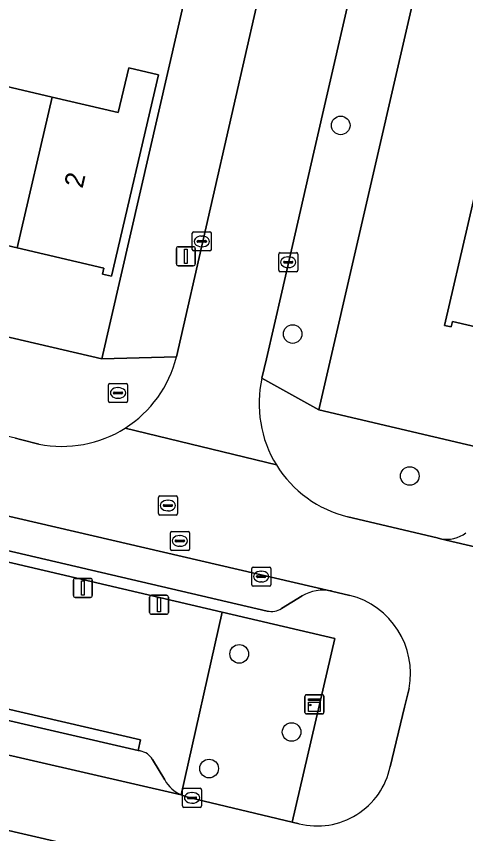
# Model space of a CAD drawing. Extents: x 163683 to 164494, y 382709 to 383872.
# Drawn here: x 163890.12 to 163913.7, y 383325.1 to 383367.98 of the extents above; entities that cross this region are included whole.
import ezdxf

# ---------------------------------------------------------------- set-up
doc = ezdxf.new("R2010")
doc.units = 0
for name, color, linetype in [('IMGEO_Boom', 7, 'Continuous'), ('IMGEO_Brandkraan', 7, 'Continuous'), ('IMGEO_Erf', 7, 'Continuous'), ('IMGEO_Groenvoorziening', 7, 'Continuous'), ('IMGEO_Kast', 7, 'Continuous'), ('IMGEO_Kolk', 7, 'Continuous'), ('IMGEO_Lichtmast', 7, 'Continuous'), ('IMGEO_Pand', 7, 'Continuous'), ('IMGEO_Pand_nummerreeks', 7, 'Continuous'), ('IMGEO_Parkeervlak_open', 7, 'Continuous'), ('IMGEO_Rijbaan_lokaal_open', 7, 'Continuous'), ('IMGEO_Rioolput', 7, 'Continuous'), ('IMGEO_Verkeersbordpaal', 7, 'Continuous'), ('IMGEO_Voetpad_open', 7, 'Continuous')]:
    doc.layers.add(name, color=color, linetype=linetype)

msp = doc.modelspace()

# ---------------------------------------------------------------- linework, layer by layer
at = {"layer": 'IMGEO_Boom'}
for centre in [(163907.144, 383362.255), (163904.622, 383351.31), (163910.77, 383343.861), (163901.817, 383334.529), (163904.566, 383330.431), (163900.236, 383328.514)]:
    msp.add_circle(centre, 0.489, dxfattribs=at)
at = {"layer": 'IMGEO_Brandkraan'}
for p, q in [((163894.955, 383347.792), (163894.955, 383348.644)), ((163895.03, 383348.718), (163895.882, 383348.718)), ((163895.443, 383348.498), (163895.468, 383348.498)), ((163895.956, 383348.644), (163895.956, 383347.792)), ((163895.214, 383348.212), (163895.214, 383348.224)), ((163895.652, 383348.175), (163895.254, 383348.175)), ((163895.257, 383348.261), (163895.655, 383348.261)), ((163895.698, 383348.224), (163895.698, 383348.212)), ((163895.882, 383347.718), (163895.03, 383347.718)), ((163895.466, 383347.938), (163895.441, 383347.938))]:
    msp.add_line(p, q, dxfattribs=at)
for points in [[(163894.955, 383347.792), (163894.955, 383348.644)], [(163895.03, 383348.718), (163895.882, 383348.718)], [(163895.956, 383348.644), (163895.956, 383347.792)], [(163895.882, 383347.718), (163895.03, 383347.718)]]:
    msp.add_lwpolyline(points, dxfattribs=at)
for centre, radius, start, end in [((163895.032, 383348.642), 0.0765, 91.552, 178.448), ((163895.032, 383348.642), 0.0765, 91.552, 178.448), ((163895.88, 383348.642), 0.0765, 1.552, 88.448), ((163895.88, 383348.642), 0.0765, 1.552, 88.448), ((163895.254, 383348.221), 0.0403, 85.8775, 175.7526), ((163895.251, 383348.211), 0.0366, 178.938, 274.7102), ((163895.655, 383348.218), 0.043, 264.8664, 352.4533), ((163895.659, 383348.223), 0.0386, 1.7309, 96.639), ((163895.032, 383347.794), 0.0765, 181.552, 268.448), ((163895.032, 383347.794), 0.0765, 181.552, 268.448), ((163895.88, 383347.794), 0.0765, 271.552, 358.448), ((163895.88, 383347.794), 0.0765, 271.552, 358.448)]:
    msp.add_arc(centre, radius, start, end, dxfattribs=at)
for centre, major_axis, ratio, start_param, end_param in [((163895.442, 383348.218), (-0.387, 0.002), 0.722429, 4.712389, 7.853982), ((163895.467, 383348.218), (-0.39, 0.002), 0.717154, 1.570796, 4.712389)]:
    msp.add_ellipse(centre, major_axis=major_axis, ratio=ratio, start_param=start_param, end_param=end_param, dxfattribs=at)
at = {"layer": 'IMGEO_Erf'}
for points in [[(163917.712, 383398.152), (163905.989, 383347.327), (163957.118, 383335.345)], [(163842.87, 383362.042), (163894.598, 383350.001), (163899.567, 383371.61)], [(163888.929, 383364.459), (163892.005, 383363.742), (163895.47, 383362.935), (163896.016, 383365.272), (163897.574, 383364.908), (163895.107, 383354.342), (163894.636, 383354.452), (163894.71, 383354.77), (163890.16, 383355.832), (163885.53, 383356.913)], [(163921.455, 383350.012), (163913.015, 383351.973), (163912.947, 383351.679), (163912.585, 383351.763), (163915.07, 383362.459)]]:
    msp.add_lwpolyline(points, dxfattribs=at)
at = {"layer": 'IMGEO_Groenvoorziening'}
for points in [[(163898.763, 383327.134), (163900.929, 383336.712), (163868.463, 383344.309), (163866.185, 383334.632), (163868.028, 383334.196), (163868.2, 383334.169)], [(163871.285, 383335.287), (163871.432, 383335.858), (163896.634, 383330.025), (163896.512, 383329.468), (163896.623, 383329.442)], [(163897.268, 383328.982), (163897.91, 383327.916)]]:
    msp.add_lwpolyline(points, dxfattribs=at)
msp.add_lwpolyline([(163906.833, 383335.33), (163900.929, 383336.712), (163898.763, 383327.134), (163899.046, 383327.03), (163899.172, 383326.999), (163904.594, 383325.708)], close=True, dxfattribs=at)
for centre, radius, start, end in [((163896.43, 383328.489), 0.972, 30.4652, 78.5436), ((163899.55, 383328.848), 1.886, 209.6209, 245.3521)]:
    msp.add_arc(centre, radius, start, end, dxfattribs=at)
at = {"layer": 'IMGEO_Kast'}
for p, q in [((163905.266, 383331.456), (163905.266, 383332.297)), ((163905.266, 383332.297), (163905.266, 383331.456)), ((163905.341, 383332.381), (163906.182, 383332.381)), ((163906.182, 383332.381), (163905.341, 383332.381)), ((163906.266, 383332.306), (163906.266, 383331.465)), ((163906.266, 383331.465), (163906.266, 383332.306)), ((163906.191, 383331.381), (163905.35, 383331.381)), ((163905.35, 383331.381), (163906.191, 383331.381))]:
    msp.add_line(p, q, dxfattribs=at)
for points in [[(163905.461, 383332.171), (163906.061, 383332.171), (163906.061, 383332.086), (163905.461, 383332.086), (163905.461, 383332.171)], [(163905.461, 383331.996), (163906.061, 383331.996), (163906.061, 383331.507), (163905.461, 383331.507), (163905.461, 383331.996)]]:
    msp.add_lwpolyline(points, dxfattribs=at)
msp.add_circle((163905.545, 383331.845), 0.0377, dxfattribs=at)
for centre, start, end in [((163905.344, 383332.303), 92.4484, 184.2845), ((163905.344, 383332.303), 92.4484, 184.2845), ((163906.188, 383332.303), 2.4484, 94.2845), ((163906.188, 383332.303), 2.4484, 94.2845), ((163905.344, 383331.459), 182.4484, 274.2845), ((163905.344, 383331.459), 182.4484, 274.2845), ((163906.188, 383331.459), 272.4484, 4.2845), ((163906.188, 383331.459), 272.4484, 4.2845)]:
    msp.add_arc(centre, 0.0779, start, end, dxfattribs=at)
at = {"layer": 'IMGEO_Kolk'}
for p, q in [((163899.352, 383355.744), (163899.352, 383356.596)), ((163899.427, 383356.67), (163900.279, 383356.67)), ((163900.353, 383356.596), (163900.353, 383355.744)), ((163899.611, 383356.164), (163899.611, 383356.176)), ((163899.654, 383356.213), (163900.052, 383356.213)), ((163899.84, 383356.45), (163899.865, 383356.45)), ((163900.095, 383356.176), (163900.095, 383356.164)), ((163900.049, 383356.127), (163899.651, 383356.127)), ((163899.863, 383355.89), (163899.838, 383355.89)), ((163900.279, 383355.67), (163899.427, 383355.67)), ((163903.889, 383354.652), (163903.889, 383355.504)), ((163903.964, 383355.578), (163904.816, 383355.578)), ((163904.377, 383355.358), (163904.402, 383355.358)), ((163904.89, 383355.504), (163904.89, 383354.652)), ((163904.148, 383355.072), (163904.148, 383355.084)), ((163904.586, 383355.035), (163904.188, 383355.035)), ((163904.191, 383355.121), (163904.589, 383355.121)), ((163904.632, 383355.084), (163904.632, 383355.072)), ((163904.816, 383354.578), (163903.964, 383354.578)), ((163904.4, 383354.798), (163904.375, 383354.798)), ((163902.472, 383338.16), (163902.472, 383339.012)), ((163902.547, 383339.086), (163903.399, 383339.086)), ((163903.473, 383339.012), (163903.473, 383338.16)), ((163902.731, 383338.58), (163902.731, 383338.592)), ((163902.774, 383338.629), (163903.172, 383338.629)), ((163902.96, 383338.866), (163902.985, 383338.866)), ((163903.215, 383338.592), (163903.215, 383338.58)), ((163903.169, 383338.543), (163902.771, 383338.543)), ((163902.983, 383338.306), (163902.958, 383338.306)), ((163903.399, 383338.086), (163902.547, 383338.086)), ((163898.915, 383327.476), (163899.767, 383327.476)), ((163898.84, 383326.55), (163898.84, 383327.402)), ((163899.142, 383327.019), (163899.54, 383327.019)), ((163899.328, 383327.256), (163899.353, 383327.256)), ((163899.841, 383327.402), (163899.841, 383326.55)), ((163899.099, 383326.97), (163899.099, 383326.982)), ((163899.537, 383326.933), (163899.139, 383326.933)), ((163899.351, 383326.696), (163899.326, 383326.696)), ((163899.583, 383326.982), (163899.583, 383326.97)), ((163899.767, 383326.476), (163898.915, 383326.476))]:
    msp.add_line(p, q, dxfattribs=at)
for points in [[(163899.352, 383355.744), (163899.352, 383356.596)], [(163899.427, 383356.67), (163900.279, 383356.67)], [(163900.353, 383356.596), (163900.353, 383355.744)], [(163900.279, 383355.67), (163899.427, 383355.67)], [(163903.889, 383354.652), (163903.889, 383355.504)], [(163903.964, 383355.578), (163904.816, 383355.578)], [(163904.89, 383355.504), (163904.89, 383354.652)], [(163904.816, 383354.578), (163903.964, 383354.578)], [(163902.472, 383338.16), (163902.472, 383339.012)], [(163902.547, 383339.086), (163903.399, 383339.086)], [(163903.473, 383339.012), (163903.473, 383338.16)], [(163903.399, 383338.086), (163902.547, 383338.086)], [(163898.915, 383327.476), (163899.767, 383327.476)], [(163898.84, 383326.55), (163898.84, 383327.402)], [(163899.841, 383327.402), (163899.841, 383326.55)], [(163899.767, 383326.476), (163898.915, 383326.476)]]:
    msp.add_lwpolyline(points, dxfattribs=at)
for centre, radius, start, end in [((163899.429, 383356.594), 0.0765, 91.552, 178.448), ((163899.429, 383356.594), 0.0765, 91.552, 178.448), ((163900.277, 383356.594), 0.0765, 1.552, 88.448), ((163900.277, 383356.594), 0.0765, 1.552, 88.448), ((163899.651, 383356.173), 0.0403, 85.8775, 175.7526), ((163899.648, 383356.163), 0.0366, 178.938, 274.7102), ((163900.052, 383356.17), 0.043, 264.8664, 352.4533), ((163900.056, 383356.175), 0.0386, 1.7309, 96.639), ((163899.429, 383355.746), 0.0765, 181.552, 268.448), ((163899.429, 383355.746), 0.0765, 181.552, 268.448), ((163900.277, 383355.746), 0.0765, 271.552, 358.448), ((163900.277, 383355.746), 0.0765, 271.552, 358.448), ((163903.966, 383355.502), 0.0765, 91.552, 178.448), ((163903.966, 383355.502), 0.0765, 91.552, 178.448), ((163904.814, 383355.502), 0.0765, 1.552, 88.448), ((163904.814, 383355.502), 0.0765, 1.552, 88.448), ((163904.188, 383355.081), 0.0403, 85.8775, 175.7526), ((163904.185, 383355.071), 0.0366, 178.938, 274.7102), ((163904.589, 383355.078), 0.043, 264.8664, 352.4533), ((163904.593, 383355.083), 0.0386, 1.7309, 96.639), ((163903.966, 383354.654), 0.0765, 181.552, 268.448), ((163903.966, 383354.654), 0.0765, 181.552, 268.448), ((163904.814, 383354.654), 0.0765, 271.552, 358.448), ((163904.814, 383354.654), 0.0765, 271.552, 358.448), ((163902.549, 383339.01), 0.0765, 91.552, 178.448), ((163902.549, 383339.01), 0.0765, 91.552, 178.448), ((163903.397, 383339.01), 0.0765, 1.552, 88.448), ((163903.397, 383339.01), 0.0765, 1.552, 88.448), ((163902.771, 383338.589), 0.0403, 85.8775, 175.7526), ((163902.768, 383338.579), 0.0366, 178.938, 274.7102), ((163903.172, 383338.586), 0.043, 264.8664, 352.4533), ((163903.176, 383338.591), 0.0386, 1.7309, 96.639), ((163902.549, 383338.162), 0.0765, 181.552, 268.448), ((163902.549, 383338.162), 0.0765, 181.552, 268.448), ((163903.397, 383338.162), 0.0765, 271.552, 358.448), ((163903.397, 383338.162), 0.0765, 271.552, 358.448), ((163898.917, 383327.4), 0.0765, 91.552, 178.448), ((163898.917, 383327.4), 0.0765, 91.552, 178.448), ((163899.765, 383327.4), 0.0765, 1.552, 88.448), ((163899.765, 383327.4), 0.0765, 1.552, 88.448), ((163899.139, 383326.979), 0.0403, 85.8775, 175.7526), ((163899.544, 383326.981), 0.0386, 1.7309, 96.639), ((163899.136, 383326.969), 0.0366, 178.938, 274.7102), ((163899.54, 383326.976), 0.043, 264.8664, 352.4533), ((163898.917, 383326.552), 0.0765, 181.552, 268.448), ((163898.917, 383326.552), 0.0765, 181.552, 268.448), ((163899.765, 383326.552), 0.0765, 271.552, 358.448), ((163899.765, 383326.552), 0.0765, 271.552, 358.448)]:
    msp.add_arc(centre, radius, start, end, dxfattribs=at)
for centre, major_axis, ratio, start_param, end_param in [((163899.839, 383356.17), (-0.387, 0.002), 0.722429, 4.712389, 7.853982), ((163899.864, 383356.17), (-0.39, 0.002), 0.717154, 1.570796, 4.712389), ((163904.376, 383355.078), (-0.387, 0.002), 0.722429, 4.712389, 7.853982), ((163904.401, 383355.078), (-0.39, 0.002), 0.717154, 1.570796, 4.712389), ((163902.959, 383338.586), (-0.387, 0.002), 0.722429, 4.712389, 7.853982), ((163902.984, 383338.586), (-0.39, 0.002), 0.717154, 1.570796, 4.712389), ((163899.327, 383326.976), (-0.387, 0.002), 0.722429, 4.712389, 7.853982), ((163899.352, 383326.976), (-0.39, 0.002), 0.717154, 1.570796, 4.712389)]:
    msp.add_ellipse(centre, major_axis=major_axis, ratio=ratio, start_param=start_param, end_param=end_param, dxfattribs=at)
at = {"layer": 'IMGEO_Lichtmast'}
for p, q in [((163898.518, 383354.989), (163898.518, 383355.789)), ((163898.518, 383355.789), (163898.518, 383354.989)), ((163898.618, 383355.889), (163899.408, 383355.889)), ((163899.408, 383355.889), (163898.618, 383355.889)), ((163899.508, 383355.789), (163899.508, 383354.989)), ((163899.508, 383354.989), (163899.508, 383355.789)), ((163899.408, 383354.889), (163898.618, 383354.889)), ((163898.618, 383354.889), (163899.408, 383354.889)), ((163893.113, 383337.59), (163893.113, 383338.39)), ((163893.113, 383338.39), (163893.113, 383337.59)), ((163893.213, 383338.49), (163894.003, 383338.49)), ((163894.003, 383338.49), (163893.213, 383338.49)), ((163894.103, 383338.39), (163894.103, 383337.59)), ((163894.103, 383337.59), (163894.103, 383338.39)), ((163894.003, 383337.49), (163893.213, 383337.49)), ((163893.213, 383337.49), (163894.003, 383337.49))]:
    msp.add_line(p, q, dxfattribs=at)
for points in [[(163898.938, 383355.764), (163899.088, 383355.764), (163899.088, 383355.014), (163898.938, 383355.014), (163898.938, 383355.764)], [(163893.533, 383338.365), (163893.683, 383338.365), (163893.683, 383337.615), (163893.533, 383337.615), (163893.533, 383338.365)]]:
    msp.add_lwpolyline(points, dxfattribs=at)
for centre, start, end in [((163898.618, 383355.789), 90, 180), ((163898.618, 383355.789), 90, 180), ((163899.408, 383355.789), 0, 90), ((163899.408, 383355.789), 360, 90), ((163898.618, 383354.989), 180, 270), ((163898.618, 383354.989), 180, 270), ((163899.408, 383354.989), 270, 0), ((163899.408, 383354.989), 270, 0), ((163893.213, 383338.39), 90, 180), ((163893.213, 383338.39), 90, 180), ((163894.003, 383338.39), 0, 90), ((163894.003, 383338.39), 360, 90), ((163893.213, 383337.59), 180, 270), ((163893.213, 383337.59), 180, 270), ((163894.003, 383337.59), 270, 0), ((163894.003, 383337.59), 270, 0)]:
    msp.add_arc(centre, 0.1, start, end, dxfattribs=at)
at = {"layer": 'IMGEO_Pand'}
for points in [[(163892.005, 383363.742), (163888.929, 383364.459), (163889.4, 383366.48), (163889.444, 383366.669), (163887.869, 383367.036), (163885.53, 383356.913), (163890.16, 383355.832)], [(163890.16, 383355.832), (163894.71, 383354.77), (163894.636, 383354.452), (163895.107, 383354.342), (163897.574, 383364.908), (163896.016, 383365.272), (163895.47, 383362.935), (163892.005, 383363.742)]]:
    msp.add_lwpolyline(points, close=True, dxfattribs=at)
msp.add_lwpolyline([(163915.07, 383362.459), (163912.585, 383351.763), (163912.947, 383351.679), (163913.015, 383351.973), (163921.455, 383350.012)], dxfattribs=at)
at = {"layer": 'IMGEO_Parkeervlak_open'}
for points in [[(163906.662, 383337.828), (163862.998, 383347.946)], [(163865.26, 383345.632), (163903.288, 383336.778)], [(163912.387, 383340.568), (163969.564, 383327.202)], [(163904.041, 383336.912), (163905.116, 383337.567)], [(163896.623, 383329.442), (163896.512, 383329.468), (163871.285, 383335.287)], [(163868.2, 383334.169), (163898.763, 383327.134)], [(163902.326, 383322.351), (163859.76, 383332.184)], [(163897.91, 383327.916), (163897.268, 383328.982)]]:
    msp.add_lwpolyline(points, dxfattribs=at)
for centre, radius, start, end in [((163912.698, 383342.215), 1.676, 259.3128, 307.3126), ((163906.228, 383335.687), 2.185, 78.5544, 120.6105), ((163903.501, 383337.765), 1.01, 257.8345, 302.3464), ((163896.43, 383328.489), 0.972, 30.4652, 78.5436), ((163899.55, 383328.848), 1.886, 209.6209, 245.3521)]:
    msp.add_arc(centre, radius, start, end, dxfattribs=at)
at = {"layer": 'IMGEO_Rijbaan_lokaal_open'}
for points in [[(163910.714, 383382.502), (163911.484, 383385.85), (163913.281, 383393.665), (163913.354, 383393.969), (163908.819, 383395.067), (163904.084, 383374.498), (163903.189, 383370.591), (163898.523, 383350.105)], [(163903.008, 383348.996), (163903.248, 383350.007), (163904.046, 383353.505), (163905.734, 383360.846), (163906.504, 383364.194), (163910.714, 383382.502)], [(163891.307, 383345.538), (163890.343, 383345.775), (163890.075, 383345.852), (163813.016, 383363.779), (163811.969, 383364.028)], [(163862.374, 383348.112), (163862.998, 383347.946), (163906.662, 383337.828), (163907.619, 383337.6)], [(163895.831, 383346.374), (163903.774, 383344.439)], [(163903.774, 383344.439), (163895.831, 383346.374)], [(163973.151, 383326.354), (163969.754, 383327.157), (163969.564, 383327.202), (163912.387, 383340.568), (163912.213, 383340.611), (163907.514, 383341.726)], [(163904.957, 383325.621), (163904.594, 383325.708), (163899.172, 383326.999), (163899.046, 383327.03), (163898.763, 383327.134), (163868.2, 383334.169), (163868.028, 383334.196), (163866.185, 383334.632), (163859.195, 383336.276)], [(163910.733, 383332.715), (163910.487, 383331.736), (163909.74, 383328.609)], [(163858.996, 383332.399), (163859.76, 383332.184), (163902.326, 383322.351), (163902.566, 383322.327), (163903.333, 383322.099)]]:
    msp.add_lwpolyline(points, dxfattribs=at)
for centre, radius, start, end in [((163892.522, 383351.598), 6.184, 302.3506, 346.0268), ((163908.961, 383347.654), 6.102, 167.293, 211.7906), ((163892.528, 383351.591), 6.175, 258.5988, 302.3406), ((163908.96, 383347.654), 6.102, 211.7946, 256.2911), ((163906.586, 383333.507), 4.222, 349.1935, 75.8384), ((163905.914, 383329.412), 3.91, 255.8381, 348.149)]:
    msp.add_arc(centre, radius, start, end, dxfattribs=at)
at = {"layer": 'IMGEO_Rioolput'}
for p, q in [((163897.574, 383341.887), (163897.574, 383342.739)), ((163897.649, 383342.813), (163898.501, 383342.813)), ((163898.062, 383342.593), (163898.087, 383342.593)), ((163898.575, 383342.739), (163898.575, 383341.887)), ((163897.833, 383342.307), (163897.833, 383342.319)), ((163898.271, 383342.27), (163897.873, 383342.27)), ((163897.876, 383342.356), (163898.274, 383342.356)), ((163898.085, 383342.033), (163898.06, 383342.033)), ((163898.317, 383342.319), (163898.317, 383342.307)), ((163898.501, 383341.813), (163897.649, 383341.813)), ((163898.203, 383340.028), (163898.203, 383340.88)), ((163898.278, 383340.954), (163899.13, 383340.954)), ((163898.691, 383340.734), (163898.716, 383340.734)), ((163899.204, 383340.88), (163899.204, 383340.028)), ((163898.462, 383340.448), (163898.462, 383340.46)), ((163898.9, 383340.411), (163898.502, 383340.411)), ((163898.505, 383340.497), (163898.903, 383340.497)), ((163898.946, 383340.46), (163898.946, 383340.448)), ((163899.13, 383339.954), (163898.278, 383339.954)), ((163898.714, 383340.174), (163898.689, 383340.174))]:
    msp.add_line(p, q, dxfattribs=at)
for points in [[(163897.574, 383341.887), (163897.574, 383342.739)], [(163897.649, 383342.813), (163898.501, 383342.813)], [(163898.575, 383342.739), (163898.575, 383341.887)], [(163898.501, 383341.813), (163897.649, 383341.813)], [(163898.203, 383340.028), (163898.203, 383340.88)], [(163898.278, 383340.954), (163899.13, 383340.954)], [(163899.204, 383340.88), (163899.204, 383340.028)], [(163899.13, 383339.954), (163898.278, 383339.954)]]:
    msp.add_lwpolyline(points, dxfattribs=at)
for centre, radius, start, end in [((163897.651, 383342.737), 0.0765, 91.552, 178.448), ((163897.651, 383342.737), 0.0765, 91.552, 178.448), ((163898.499, 383342.737), 0.0765, 1.552, 88.448), ((163898.499, 383342.737), 0.0765, 1.552, 88.448), ((163897.873, 383342.316), 0.0403, 85.8775, 175.7526), ((163897.87, 383342.306), 0.0366, 178.938, 274.7102), ((163898.274, 383342.313), 0.043, 264.8664, 352.4533), ((163898.278, 383342.318), 0.0386, 1.7309, 96.639), ((163897.651, 383341.889), 0.0765, 181.552, 268.448), ((163897.651, 383341.889), 0.0765, 181.552, 268.448), ((163898.499, 383341.889), 0.0765, 271.552, 358.448), ((163898.499, 383341.889), 0.0765, 271.552, 358.448), ((163898.28, 383340.878), 0.0765, 91.552, 178.448), ((163898.28, 383340.878), 0.0765, 91.552, 178.448), ((163899.128, 383340.878), 0.0765, 1.552, 88.448), ((163899.128, 383340.878), 0.0765, 1.552, 88.448), ((163898.502, 383340.457), 0.0403, 85.8775, 175.7526), ((163898.499, 383340.447), 0.0366, 178.938, 274.7102), ((163898.903, 383340.454), 0.043, 264.8664, 352.4533), ((163898.907, 383340.459), 0.0386, 1.7309, 96.639), ((163898.28, 383340.03), 0.0765, 181.552, 268.448), ((163898.28, 383340.03), 0.0765, 181.552, 268.448), ((163899.128, 383340.03), 0.0765, 271.552, 358.448), ((163899.128, 383340.03), 0.0765, 271.552, 358.448)]:
    msp.add_arc(centre, radius, start, end, dxfattribs=at)
for centre, major_axis, ratio, start_param, end_param in [((163898.061, 383342.313), (-0.387, 0.002), 0.722429, 4.712389, 7.853982), ((163898.086, 383342.313), (-0.39, 0.002), 0.717154, 1.570796, 4.712389), ((163898.69, 383340.454), (-0.387, 0.002), 0.722429, 4.712389, 7.853982), ((163898.715, 383340.454), (-0.39, 0.002), 0.717154, 1.570796, 4.712389)]:
    msp.add_ellipse(centre, major_axis=major_axis, ratio=ratio, start_param=start_param, end_param=end_param, dxfattribs=at)
at = {"layer": 'IMGEO_Verkeersbordpaal'}
for p, q in [((163897.114, 383336.706), (163897.114, 383337.506)), ((163897.114, 383337.506), (163897.114, 383336.706)), ((163897.214, 383337.606), (163898.004, 383337.606)), ((163898.004, 383337.606), (163897.214, 383337.606)), ((163898.104, 383337.506), (163898.104, 383336.706)), ((163898.104, 383336.706), (163898.104, 383337.506)), ((163898.004, 383336.606), (163897.214, 383336.606)), ((163897.214, 383336.606), (163898.004, 383336.606))]:
    msp.add_line(p, q, dxfattribs=at)
msp.add_lwpolyline([(163897.534, 383337.481), (163897.684, 383337.481), (163897.684, 383336.731), (163897.534, 383336.731), (163897.534, 383337.481)], dxfattribs=at)
for centre, start, end in [((163897.214, 383337.506), 90, 180), ((163897.214, 383337.506), 90, 180), ((163898.004, 383337.506), 0, 90), ((163898.004, 383337.506), 360, 90), ((163897.214, 383336.706), 180, 270), ((163897.214, 383336.706), 180, 270), ((163898.004, 383336.706), 270, 0), ((163898.004, 383336.706), 270, 0)]:
    msp.add_arc(centre, 0.1, start, end, dxfattribs=at)
at = {"layer": 'IMGEO_Voetpad_open'}
for points in [[(163913.996, 383396.57), (163913.908, 383396.293), (163913.354, 383393.969), (163913.281, 383393.665), (163911.484, 383385.85), (163910.714, 383382.502), (163906.504, 383364.194), (163905.734, 383360.846), (163904.046, 383353.505), (163903.248, 383350.007), (163903.008, 383348.996), (163905.989, 383347.327), (163917.712, 383398.152)], [(163900.467, 383377.007), (163900.451, 383376.938), (163900.087, 383375.322), (163900.022, 383375.339), (163899.977, 383375.155), (163899.173, 383371.71), (163899.567, 383371.61), (163894.598, 383350.001), (163898.523, 383350.105), (163903.189, 383370.591), (163902.762, 383370.701), (163903.662, 383374.604), (163904.084, 383374.498), (163908.819, 383395.067)], [(163898.523, 383350.105), (163894.598, 383350.001), (163842.87, 383362.042)], [(163905.989, 383347.327), (163903.008, 383348.996)], [(163915.561, 383341.678), (163956.365, 383332.095), (163957.118, 383335.345), (163905.989, 383347.327)], [(163859.195, 383336.276), (163861.514, 383345.905), (163868.463, 383344.309), (163900.929, 383336.712), (163906.833, 383335.33), (163904.594, 383325.708), (163904.957, 383325.621)], [(163903.288, 383336.778), (163865.26, 383345.632)], [(163890.075, 383345.852), (163890.343, 383345.775), (163891.307, 383345.538)], [(163907.514, 383341.726), (163912.213, 383340.611), (163912.387, 383340.568)], [(163907.619, 383337.6), (163906.662, 383337.828)], [(163905.116, 383337.567), (163904.041, 383336.912)], [(163909.74, 383328.609), (163910.487, 383331.736), (163910.733, 383332.715)]]:
    msp.add_lwpolyline(points, dxfattribs=at)
msp.add_lwpolyline([(163896.512, 383329.468), (163896.634, 383330.025), (163871.432, 383335.858), (163871.285, 383335.287)], close=True, dxfattribs=at)
for centre, radius, start, end in [((163892.522, 383351.598), 6.184, 302.3506, 346.0268), ((163908.961, 383347.654), 6.102, 167.293, 211.7906), ((163892.528, 383351.591), 6.175, 258.5988, 302.3406), ((163908.96, 383347.654), 6.102, 211.7946, 256.2911), ((163912.698, 383342.215), 1.676, 259.3128, 307.3126), ((163906.228, 383335.687), 2.185, 78.5544, 120.6105), ((163906.586, 383333.507), 4.222, 349.1935, 75.8384), ((163903.501, 383337.765), 1.01, 257.8345, 302.3464), ((163905.914, 383329.412), 3.91, 255.8381, 348.149)]:
    msp.add_arc(centre, radius, start, end, dxfattribs=at)

# ---------------------------------------------------------------- texts
at = {"layer": 'IMGEO_Pand_nummerreeks'}
msp.add_text('2', height=1, rotation=76.8578, dxfattribs=at).set_placement((163893.588, 383358.918))

doc.saveas('drawing.dxf')
